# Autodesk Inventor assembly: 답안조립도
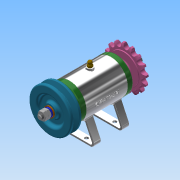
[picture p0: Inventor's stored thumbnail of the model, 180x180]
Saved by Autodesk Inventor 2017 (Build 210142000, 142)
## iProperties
Part Number: 답안조립도
Material: 일반
Document SubType Name: Assembly
Designer: Administrator
Author: Administrator
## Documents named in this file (16)
- C:\Users\Administrator\Desktop\711206V1008\답안조립도.iam
- C:\Users\Administrator\Desktop\711206V1008\본체.ipt
- C:\Users\Administrator\Desktop\711206V1008\711206V1008공용부품\V벨트풀리.ipt
- C:\Users\Administrator\Desktop\711206V1008\711206V1008공용부품\너트 M8.ipt
- C:\Users\Administrator\Desktop\711206V1008\711206V1008공용부품\니플 M6 x 0.75.ipt
- C:\Users\Administrator\Desktop\711206V1008\711206V1008공용부품\베어링 6002.ipt
- C:\Users\Administrator\Desktop\711206V1008\711206V1008공용부품\볼트 M4 x 12.ipt
- C:\Users\Administrator\Desktop\711206V1008\711206V1008공용부품\볼트 M6 x 8.ipt
- C:\Users\Administrator\Desktop\711206V1008\711206V1008공용부품\스프로킷.ipt
- C:\Users\Administrator\Desktop\711206V1008\711206V1008공용부품\스프링와셔 8.ipt
- C:\Users\Administrator\Desktop\711206V1008\711206V1008공용부품\오일 실 15 x 25 x 7.ipt
- C:\Users\Administrator\Desktop\711206V1008\711206V1008공용부품\와셔 6 x 11.5.ipt
- C:\Users\Administrator\Desktop\711206V1008\711206V1008공용부품\와셔 8 x 17.ipt
- C:\Users\Administrator\Desktop\711206V1008\711206V1008공용부품\축.ipt
- C:\Users\Administrator\Desktop\711206V1008\711206V1008공용부품\커버.ipt
- C:\Users\Administrator\Desktop\711206V1008\711206V1008공용부품\키 3 x 3.ipt
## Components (11 placed, 3 different names)
1. V벨트풀리:1
2. KS B 2023 6002 - 15 x 32 x 9:1
3. KS B 2023 6002 - 15 x 32 x 9:2
4. ISO 4762 M4 x 12:1
5. ISO 4762 M4 x 12:2
6. ISO 4762 M4 x 12:3
7. ISO 4762 M4 x 12:4
8. ISO 4762 M4 x 12:5
9. ISO 4762 M4 x 12:6
10. ISO 4762 M4 x 12:7
11. ISO 4762 M4 x 12:8
